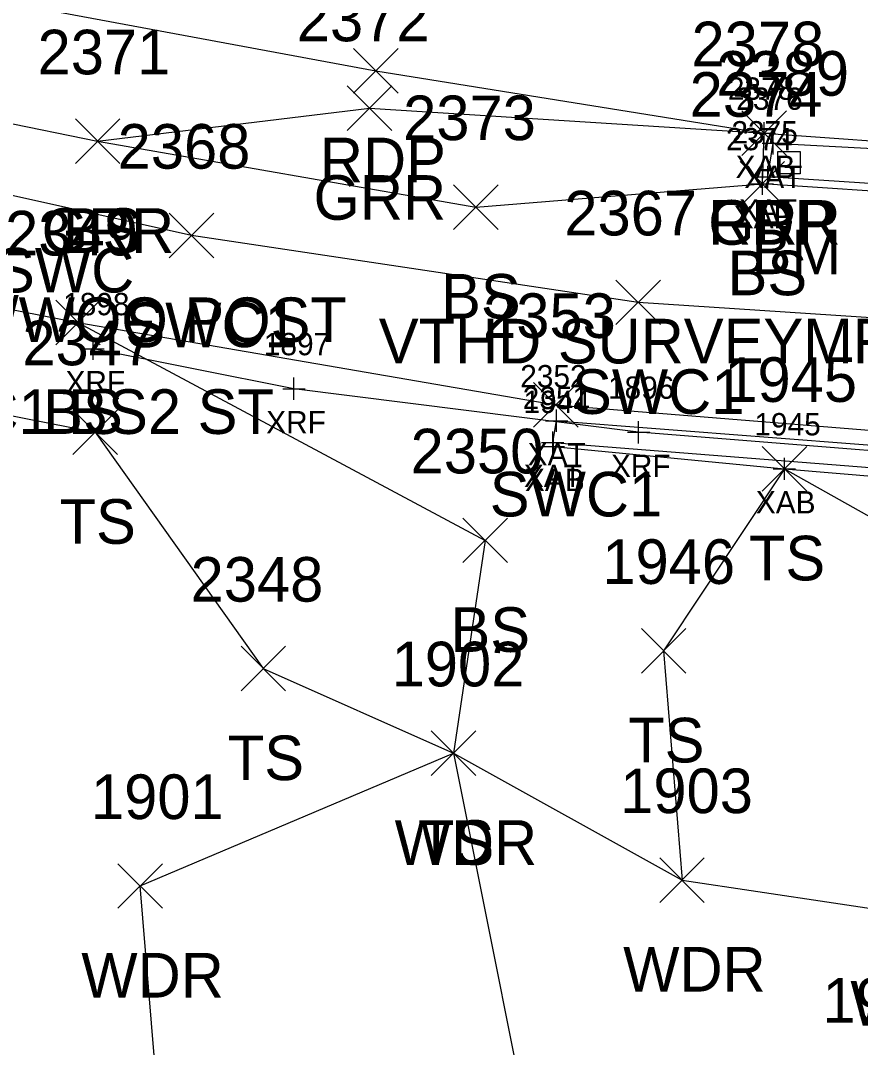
# Model space of a CAD drawing. Extents: x 1461855 to 1464118, y 556196 to 557441.
# Drawn here: x 1462099.03 to 1462136.67, y 556387.14 to 556433.17 of the extents above; entities that cross this region are included whole.
import ezdxf

# ---------------------------------------------------------------- set-up
doc = ezdxf.new("R2010")
doc.units = 0
for name, color, linetype in [('B_A', 7, 'Continuous'), ('B_I', 7, 'Continuous'), ('B_TIC', 7, 'Continuous'), ('BR', 7, 'Continuous'), ('BSUBM', 7, 'Continuous'), ('C_A', 7, 'Continuous'), ('C_C', 7, 'Continuous'), ('C_I', 7, 'Continuous'), ('CPBM', 7, 'Continuous'), ('L_A', 7, 'Continuous'), ('L_I', 7, 'Continuous'), ('L_TIC', 7, 'Continuous'), ('LAWA', 7, 'Continuous'), ('LELB', 7, 'Continuous'), ('P_A', 7, 'Continuous'), ('P_I', 7, 'Continuous'), ('P_TIC', 7, 'Continuous'), ('PET', 7, 'Continuous'), ('R_A', 7, 'Continuous'), ('R_C', 7, 'Continuous'), ('R_I', 7, 'Continuous'), ('R_TIC', 7, 'Continuous'), ('RGR', 7, 'Continuous'), ('RSW', 7, 'Continuous')]:
    doc.layers.add(name, color=color, linetype=linetype)

msp = doc.modelspace()

# ---------------------------------------------------------------- linework, layer by layer
at = {"layer": 'B_TIC'}
for p, q in [((1462132.363, 556428.115), (1462132.439, 556428.115)), ((1462132.769, 556427.663), (1462132.844, 556427.663)), ((1462132.524, 556426.157), (1462132.6, 556426.157)), ((1462132.281, 556425.852), (1462132.356, 556425.852)), ((1462102.288, 556418.456), (1462102.363, 556418.456)), ((1462111.284, 556416.663), (1462111.36, 556416.663)), ((1462123.059, 556415.224), (1462123.134, 556415.224)), ((1462126.736, 556414.71), (1462126.811, 556414.71)), ((1462122.888, 556414.252), (1462122.963, 556414.252)), ((1462122.888, 556414.252), (1462122.963, 556414.252)), ((1462122.92, 556414.073), (1462122.995, 556414.073)), ((1462133.269, 556413.072), (1462133.344, 556413.072))]:
    msp.add_line(p, q, dxfattribs=at)
for points in [[(1462132.36, 556427.615), (1462132.36, 556428.615)], [(1462131.86, 556428.115), (1462132.86, 556428.115)], [(1462132.765, 556427.163), (1462132.765, 556428.163)], [(1462132.265, 556427.663), (1462133.265, 556427.663)], [(1462132.521, 556425.657), (1462132.521, 556426.657)], [(1462132.021, 556426.157), (1462133.021, 556426.157)], [(1462132.277, 556425.352), (1462132.277, 556426.352)], [(1462131.777, 556425.852), (1462132.777, 556425.852)], [(1462102.284, 556417.956), (1462102.284, 556418.956)], [(1462101.784, 556418.456), (1462102.784, 556418.456)], [(1462111.281, 556416.163), (1462111.281, 556417.163)], [(1462110.781, 556416.663), (1462111.781, 556416.663)], [(1462123.055, 556414.724), (1462123.055, 556415.724)], [(1462122.555, 556415.224), (1462123.555, 556415.224)], [(1462126.732, 556414.21), (1462126.732, 556415.21)], [(1462122.884, 556413.752), (1462122.884, 556414.752)], [(1462122.884, 556413.752), (1462122.884, 556414.752)], [(1462122.916, 556413.573), (1462122.916, 556414.573)], [(1462126.232, 556414.71), (1462127.232, 556414.71)], [(1462122.384, 556414.252), (1462123.384, 556414.252)], [(1462122.384, 556414.252), (1462123.384, 556414.252)], [(1462122.416, 556414.073), (1462123.416, 556414.073)], [(1462133.265, 556412.572), (1462133.265, 556413.572)], [(1462132.765, 556413.072), (1462133.765, 556413.072)]]:
    msp.add_lwpolyline(points, dxfattribs=at)
at = {"layer": 'BR'}
msp.add_lwpolyline([(1462356.157, 556401.791), (1462336.856, 556402.851), (1462260.866, 556407.054), (1462205.402, 556409.871), (1462146.909, 556413.108), (1462126.732, 556414.71), (1462111.281, 556416.663), (1462102.284, 556418.456)], dxfattribs=at)
at = {"layer": 'BSUBM'}
for points in [[(1462122.916, 556414.073), (1462133.265, 556413.072), (1462141.99, 556412.339), (1462147.378, 556411.884), (1462147.86, 556412.274), (1462148.284, 556423.269), (1462148.263, 556423.598), (1462148.369, 556425.059), (1462150.384, 556424.945), (1462152.207, 556451.055), (1462147.584, 556451.265)], [(1462146.772, 556425.051), (1462139.881, 556425.331), (1462132.277, 556425.852), (1462132.36, 556428.115)], [(1462148.273, 556425.131), (1462132.521, 556426.157), (1462132.765, 556427.663), (1462148.418, 556426.831)], [(1462122.884, 556414.252), (1462123.055, 556415.224), (1462146.277, 556413.431), (1462146.711, 556421.317), (1462146.772, 556425.051)], [(1462122.884, 556414.252), (1462146.561, 556412.382), (1462146.553, 556413.419), (1462146.926, 556421.311), (1462147.933, 556421.317), (1462148.172, 556424.971), (1462146.772, 556425.051)]]:
    msp.add_lwpolyline(points, dxfattribs=at)
at = {"layer": 'CPBM'}
for p, q in [((1462132.978, 556426.295), (1462132.978, 556427.295)), ((1462132.978, 556427.295), (1462133.978, 556427.295)), ((1462133.978, 556427.295), (1462133.978, 556426.295)), ((1462133.48, 556426.796), (1462133.48, 556426.796)), ((1462133.48, 556426.796), (1462133.48, 556426.796)), ((1462133.978, 556426.295), (1462132.978, 556426.295))]:
    msp.add_line(p, q, dxfattribs=at)
at = {"layer": 'L_TIC'}
for points in [[(1462101.486, 556426.753), (1462103.486, 556428.753)], [(1462103.486, 556426.753), (1462101.486, 556428.753)], [(1462131.277, 556424.852), (1462133.277, 556426.852)], [(1462133.277, 556424.852), (1462131.277, 556426.852)], [(1462118.437, 556423.804), (1462120.437, 556425.804)], [(1462120.437, 556423.804), (1462118.437, 556425.804)], [(1462100.605, 556418.636), (1462102.605, 556420.636)], [(1462102.605, 556418.636), (1462100.605, 556420.636)], [(1462101.371, 556413.712), (1462103.371, 556415.712)], [(1462103.371, 556413.712), (1462101.371, 556415.712)], [(1462132.265, 556412.072), (1462134.265, 556414.072)], [(1462134.265, 556412.072), (1462132.265, 556414.072)], [(1462132.265, 556412.072), (1462134.265, 556414.072)], [(1462134.265, 556412.072), (1462132.265, 556414.072)], [(1462118.858, 556408.867), (1462120.858, 556410.867)], [(1462120.858, 556408.867), (1462118.858, 556410.867)], [(1462126.854, 556403.913), (1462128.854, 556405.913)], [(1462128.854, 556403.913), (1462126.854, 556405.913)], [(1462108.911, 556403.118), (1462110.911, 556405.118)], [(1462110.911, 556403.118), (1462108.911, 556405.118)], [(1462117.433, 556399.322), (1462119.433, 556401.322)], [(1462119.433, 556399.322), (1462117.433, 556401.322)], [(1462117.433, 556399.322), (1462119.433, 556401.322)], [(1462119.433, 556399.322), (1462117.433, 556401.322)], [(1462103.39, 556393.374), (1462105.39, 556395.374)], [(1462105.39, 556393.374), (1462103.39, 556395.374)], [(1462127.676, 556393.64), (1462129.676, 556395.64)], [(1462129.676, 556393.64), (1462127.676, 556395.64)]]:
    msp.add_lwpolyline(points, dxfattribs=at)
at = {"layer": 'LAWA'}
msp.add_lwpolyline([(1462103.87, 556357.158), (1462105.529, 556380.621), (1462104.39, 556394.374), (1462118.433, 556400.322), (1462128.676, 556394.64), (1462138.861, 556393.111), (1462145.159, 556394.919)], dxfattribs=at)
at = {"layer": 'LELB'}
for points in [[(1462080.674, 556435.558), (1462093.708, 556429.546), (1462102.486, 556427.753), (1462119.437, 556424.804), (1462132.277, 556425.852)], [(1462101.605, 556419.636), (1462119.858, 556409.867)], [(1462067.55, 556365.344), (1462070.433, 556381.041), (1462073.873, 556402.699), (1462075.308, 556410.125), (1462077.564, 556419.157), (1462088.19, 556417.505), (1462102.371, 556414.712), (1462109.911, 556404.118)], [(1462133.265, 556413.072), (1462127.854, 556404.913)], [(1462133.265, 556413.072), (1462143.915, 556407.092)], [(1462119.858, 556409.867), (1462118.433, 556400.322)], [(1462127.854, 556404.913), (1462128.676, 556394.64)], [(1462109.911, 556404.118), (1462118.433, 556400.322)], [(1462118.433, 556400.322), (1462122.785, 556378.567), (1462135.676, 556373.74), (1462141.415, 556356.754), (1462144.252, 556338.025), (1462134.758, 556334.037), (1462116.955, 556337.28)]]:
    msp.add_lwpolyline(points, dxfattribs=at)
at = {"layer": 'P_TIC'}
for points in [[(1462113.96, 556429.915), (1462115.96, 556431.915)], [(1462115.96, 556429.915), (1462113.96, 556431.915)], [(1462131.36, 556427.115), (1462133.36, 556429.115)], [(1462133.36, 556427.115), (1462131.36, 556429.115)]]:
    msp.add_lwpolyline(points, dxfattribs=at)
at = {"layer": 'PET'}
msp.add_lwpolyline([(1461991.983, 556503.178), (1462006.217, 556483.047), (1462018.561, 556469.328), (1462030.094, 556457.862), (1462048.811, 556444.893), (1462057.177, 556443.273), (1462083.113, 556436.833), (1462114.96, 556430.915), (1462132.36, 556428.115), (1462140.707, 556427.525), (1462147.35, 556427.105), (1462147.933, 556438.199), (1462148.835, 556449.192)], dxfattribs=at)
at = {"layer": 'R_TIC'}
for points in [[(1462113.673, 556428.235), (1462115.673, 556430.235)], [(1462115.673, 556428.235), (1462113.673, 556430.235)], [(1462131.36, 556427.115), (1462133.36, 556429.115)], [(1462133.36, 556427.115), (1462131.36, 556429.115)], [(1462101.486, 556426.753), (1462103.486, 556428.753)], [(1462103.486, 556426.753), (1462101.486, 556428.753)], [(1462105.689, 556422.525), (1462107.689, 556424.525)], [(1462107.689, 556422.525), (1462105.689, 556424.525)], [(1462125.708, 556419.534), (1462127.708, 556421.534)], [(1462127.708, 556419.534), (1462125.708, 556421.534)], [(1462100.605, 556418.636), (1462102.605, 556420.636)], [(1462102.605, 556418.636), (1462100.605, 556420.636)], [(1462122.021, 556414.938), (1462124.021, 556416.938)], [(1462124.021, 556414.938), (1462122.021, 556416.938)]]:
    msp.add_lwpolyline(points, dxfattribs=at)
at = {"layer": 'RGR'}
msp.add_lwpolyline([(1462102.486, 556427.753), (1462114.673, 556429.235), (1462132.36, 556428.115)], dxfattribs=at)
at = {"layer": 'RSW'}
msp.add_lwpolyline([(1462058.072, 556430.77), (1462057.957, 556426.117), (1462064.419, 556425.318), (1462073.508, 556425.137), (1462101.605, 556419.636), (1462123.021, 556415.938), (1462146.097, 556414.079), (1462146.48, 556419.221), (1462126.708, 556420.534), (1462106.689, 556423.525), (1462095.675, 556425.977)], dxfattribs=at)

# ---------------------------------------------------------------- texts
at = {"layer": 'B_A'}
for s, p in [('XAB', (1462131.08, 556426.115)), ('XAT', (1462131.47, 556425.663)), ('XAT', (1462131.226, 556424.157)), ('XAB', (1462130.998, 556423.852)), ('XRF', (1462101.044, 556416.456)), ('XRF', (1462110.041, 556414.663)), ('XAT', (1462121.76, 556413.224)), ('XRF', (1462125.492, 556412.71)), ('XAT', (1462121.589, 556412.252)), ('XAT', (1462121.589, 556412.252)), ('XAB', (1462121.637, 556412.073)), ('XAB', (1462131.986, 556411.072))]:
    msp.add_text(s, height=1, dxfattribs=at).set_placement(p)
at = {"layer": 'B_I'}
for s, p in [('2378', (1462130.73, 556429.615)), ('2376', (1462131.108, 556429.163)), ('2374', (1462130.648, 556427.352)), ('2375', (1462130.891, 556427.657)), ('1898', (1462100.938, 556419.956)), ('1897', (1462109.935, 556418.163)), ('2352', (1462121.425, 556416.724)), ('1896', (1462125.358, 556416.21)), ('2351', (1462121.538, 556415.752)), ('2351', (1462121.538, 556415.752)), ('1944', (1462121.57, 556415.573)), ('1945', (1462131.919, 556414.572))]:
    msp.add_text(s, height=1, dxfattribs=at).set_placement(p)
at = {"layer": 'C_A'}
msp.add_text('BM', height=2, dxfattribs=at).set_placement((1462131.795, 556421.796))
at = {"layer": 'C_C'}
msp.add_text('VTHD SURVEYMRK ELEV=', height=2, dxfattribs=at).set_placement((1462115.087, 556417.796))
at = {"layer": 'C_I'}
msp.add_text('2389', height=2, dxfattribs=at).set_placement((1462130.213, 556429.796))
at = {"layer": 'L_A'}
for s, p in [('BS', (1462100.927, 556422.753)), ('BS', (1462130.718, 556420.852)), ('BS', (1462117.878, 556419.804)), ('BS', (1462100.046, 556414.636)), ('TS', (1462100.78, 556409.712)), ('TS', (1462131.675, 556408.072)), ('TS', (1462131.675, 556408.072)), ('BS', (1462118.299, 556404.867)), ('TS', (1462126.264, 556399.913)), ('TS', (1462108.32, 556399.118)), ('WDR', (1462115.796, 556395.322)), ('TS', (1462116.843, 556395.322)), ('WDR', (1462126.039, 556389.64)), ('WDR', (1462101.753, 556389.374)), ('WDR', (1462136.224, 556388.111))]:
    msp.add_text(s, height=2, dxfattribs=at).set_placement(p)
at = {"layer": 'L_I'}
for s, p in [('2371', (1462099.793, 556430.753)), ('2374', (1462129.018, 556428.852)), ('2373', (1462116.178, 556427.804)), ('2349', (1462098.337, 556422.636)), ('2347', (1462099.111, 556417.712)), ('1945', (1462130.572, 556416.072)), ('1945', (1462130.572, 556416.072)), ('2350', (1462116.512, 556412.867)), ('1946', (1462125.106, 556407.913)), ('2348', (1462106.651, 556407.118)), ('1902', (1462115.662, 556403.322)), ('1902', (1462115.662, 556403.322)), ('1901', (1462102.186, 556397.374)), ('1903', (1462125.905, 556397.64)), ('1930', (1462134.974, 556388.246))]:
    msp.add_text(s, height=2, dxfattribs=at).set_placement(p)
at = {"layer": 'P_A'}
for p in [(1462112.448, 556425.915), (1462129.848, 556423.115)]:
    msp.add_text('RDP', height=2, dxfattribs=at).set_placement(p)
at = {"layer": 'P_I'}
msp.add_text('2378', height=2, dxfattribs=at).set_placement((1462129.1, 556431.115))
at = {"layer": 'R_A'}
for s, p in [('GRR', (1462112.161, 556424.235)), ('GRR', (1462129.848, 556423.115)), ('GRR', (1462099.974, 556422.753)), ('SWC1 SWC', (1462089.416, 556420.977)), ('SWC1 SWC', (1462089.416, 556420.977)), ('SWC1', (1462103.729, 556418.525)), ('SWC1', (1462123.748, 556415.534)), ('SWC1 BS2 ST', (1462092.699, 556414.636)), ('SWC1', (1462120.06, 556410.938))]:
    msp.add_text(s, height=2, dxfattribs=at).set_placement(p)
at = {"layer": 'R_C'}
msp.add_text('SGR W/WOO POST', height=2, dxfattribs=at).set_placement((1462089.139, 556418.753))
at = {"layer": 'R_I'}
for s, p in [('2372', (1462111.413, 556432.235)), ('2378', (1462129.1, 556431.115)), ('2371', (1462099.793, 556430.753)), ('2368', (1462103.382, 556426.525)), ('2367', (1462123.401, 556423.534)), ('2349', (1462098.337, 556422.636)), ('2353', (1462119.761, 556418.938))]:
    msp.add_text(s, height=2, dxfattribs=at).set_placement(p)

doc.saveas('drawing.dxf')
